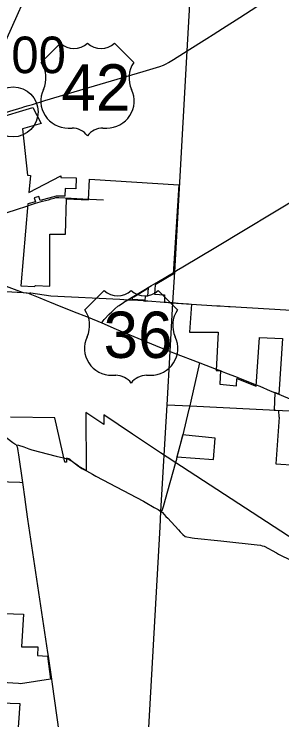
# Model space of a CAD drawing. Extents: x 1729596 to 1934326, y 644115 to 911751.
# Drawn here: x 1815592 to 1823628, y 824548 to 845758 of the extents above; entities that cross this region are included whole.
import ezdxf

# ---------------------------------------------------------------- set-up
doc = ezdxf.new("R2010")
doc.units = 0
for name, color, linetype in [('Default', 7, 'Continuous'), ('GM_X_City_Street', 7, 'Continuous'), ('GM_X_Corporation', 7, 'Continuous'), ('GM_X_County_Road', 7, 'Continuous'), ('GM_X_State_Route', 7, 'Continuous'), ('GM_X_Township', 7, 'Continuous'), ('GM_X_Township_Road', 7, 'Continuous'), ('GM_X_US_Route', 7, 'Continuous'), ('GM_X_US_Shield', 7, 'Continuous')]:
    doc.layers.add(name, color=color, linetype=linetype)

msp = doc.modelspace()

# ---------------------------------------------------------------- linework, layer by layer
at = {"layer": 'Default'}
msp.add_circle((1815562, 842819), 750, dxfattribs=at)
at = {"layer": 'GM_X_City_Street'}
for points in [[(1813943, 839357), (1814716, 839584), (1815637, 839875), (1816002, 840001), (1816050, 840016)], [(1816021, 837368), (1816062, 837380), (1816090, 837381), (1816690, 837295), (1818762, 837191), (1819004, 837172)], [(1819004, 837172), (1819134, 837175), (1819472, 837149)], [(1819524, 837145), (1819604, 837139), (1820097, 837105)], [(1820652, 833075), (1820849, 833886), (1820873, 833984), (1820908, 834123), (1821164, 835274)], [(1817072, 832421), (1817099, 832415), (1817170, 832396)], [(1820438, 832263), (1820471, 832388), (1820478, 832416)]]:
    msp.add_lwpolyline(points, dxfattribs=at)
at = {"layer": 'GM_X_Corporation'}
for points in [[(1815016, 842610), (1816153, 842951), (1816403, 842466), (1815846, 842310), (1815989, 840914), (1816080, 840907), (1816036, 840400), (1816992, 840894), (1816992, 840847), (1817454, 840834), (1817443, 840510), (1817122, 840521), (1817110, 840282), (1816854, 840287), (1816369, 840160), (1816334, 840281), (1816195, 840241), (1816230, 840120), (1816007, 840055), (1815797, 837596), (1816204, 837568), (1816230, 837602), (1816665, 837580), (1816663, 839149), (1817135, 839141), (1817168, 840204), (1817823, 840172), (1817852, 840795), (1820532, 840624), (1820362, 837942), (1819824, 837620), (1819808, 837343), (1820104, 837324), (1820105, 837097), (1820468, 837073), (1820915, 837044), (1820852, 836201), (1821717, 836195), (1821656, 835046), (1821781, 835050), (1821769, 834633), (1822268, 834587), (1822281, 834808), (1822854, 834577), (1822956, 836039), (1823645, 836005), (1823540, 834336), (1823415, 834383), (1823397, 833851), (1823528, 833845), (1823535, 833649), (1823542, 833643), (1823444, 832245), (1824058, 832202)], [(1824031, 829939), (1819982, 832569), (1819654, 832789), (1819142, 833130), (1818281, 833718), (1818286, 833421), (1817747, 833788), (1817756, 832046), (1817667, 832094), (1817528, 832169), (1817473, 832209), (1817387, 832271), (1817263, 832384), (1817160, 832409), (1817160, 832297), (1817114, 832297), (1816814, 833623), (1815483, 833646)], [(1811009, 827882), (1815869, 827729), (1815809, 826748), (1816301, 826739), (1816293, 826483), (1816593, 826467), (1816684, 825773), (1815779, 825630), (1815726, 825640), (1815222, 825670)], [(1815180, 825063), (1815759, 825045), (1815628, 823017)]]:
    msp.add_lwpolyline(points, dxfattribs=at)
for points in [[(1819526, 837135), (1819535, 837296), (1819609, 837287), (1819623, 837519), (1819182, 837253), (1819135, 837235), (1819132, 837195), (1819476, 837173), (1819474, 837138)], [(1820476, 832454), (1821573, 832377), (1821623, 833012), (1820645, 833115), (1820621, 833009), (1820595, 832898)]]:
    msp.add_lwpolyline(points, close=True, dxfattribs=at)
at = {"layer": 'GM_X_County_Road'}
for points in [[(1814101, 842164), (1814760, 843649), (1815210, 844662), (1816320, 847160), (1816351, 847229), (1816426, 847398), (1816452, 847455)], [(1819472, 837149), (1819494, 837147), (1819524, 837145)], [(1820097, 837105), (1820163, 837101), (1820305, 837091)], [(1820305, 837091), (1820358, 837087), (1820517, 837071), (1820825, 837049)], [(1820825, 837049), (1820913, 837042), (1821680, 836994), (1821777, 836987), (1822028, 836972), (1822074, 836969)], [(1822074, 836969), (1824417, 836829)], [(1815650, 832818), (1815609, 832834), (1815550, 832877), (1815172, 833164), (1814933, 833350), (1814868, 833401), (1814625, 833586), (1814048, 834029), (1813975, 834088), (1813947, 834115), (1813922, 834145), (1813910, 834164)], [(1815650, 832818), (1815681, 832754), (1815696, 832701), (1815707, 832636), (1815724, 832514), (1815839, 831685), (1815910, 831182), (1815924, 831087), (1815997, 830585), (1816596, 826570), (1816611, 826462)], [(1816611, 826462), (1816709, 825776), (1816721, 825692)], [(1816721, 825692), (1817014, 823620), (1817048, 823324), (1817073, 823174), (1817376, 823219), (1817730, 823275), (1817816, 823287), (1818034, 823286), (1819167, 823275), (1819464, 823265), (1819525, 823263), (1819568, 823254)]]:
    msp.add_lwpolyline(points, dxfattribs=at)
at = {"layer": 'GM_X_State_Route'}
for points in [[(1820468, 838053), (1820655, 838166), (1821648, 838759), (1824240, 840319)], [(1813129, 838411), (1813340, 838332), (1813710, 838195), (1813746, 838181), (1814002, 838086), (1814499, 837901), (1814621, 837856), (1814811, 837785), (1814899, 837753), (1814979, 837723), (1815024, 837706), (1815354, 837583), (1815358, 837582), (1815752, 837432), (1815862, 837391)], [(1819182, 837279), (1819382, 837398), (1819716, 837599), (1819921, 837722), (1820411, 838018), (1820468, 838053)], [(1818870, 837089), (1818887, 837100), (1819004, 837172), (1819182, 837279)], [(1818616, 836904), (1818704, 836977), (1818742, 837004), (1818870, 837089)], [(1818221, 836484), (1818267, 836536), (1818298, 836577), (1818447, 836739), (1818522, 836815), (1818613, 836902), (1818616, 836904)]]:
    msp.add_lwpolyline(points, dxfattribs=at)
at = {"layer": 'GM_X_Township'}
for points in [[(1820182, 834021), (1820274, 835623), (1820357, 837080), (1820411, 838018), (1820789, 844650), (1820950, 847472), (1821204, 851968), (1821306, 853784), (1821743, 860915)], [(1819571, 823253), (1819973, 830336), (1820000, 830812), (1820182, 834021), (1820873, 833984), (1824840, 833781), (1824931, 833776), (1825545, 833759), (1825602, 833752), (1827748, 833636), (1831529, 833453), (1832327, 833414), (1835297, 833263), (1838313, 833094), (1838887, 833066), (1838934, 833082), (1842052, 832856), (1843609, 832772), (1846971, 832575), (1846863, 830918), (1846854, 830870), (1846509, 825988), (1846205, 821378)]]:
    msp.add_lwpolyline(points, dxfattribs=at)
at = {"layer": 'GM_X_Township_Road'}
for points in [[(1816050, 840016), (1816237, 840077), (1816448, 840141), (1816624, 840179), (1816708, 840206), (1816793, 840229), (1816843, 840243), (1816931, 840248), (1817301, 840230), (1817654, 840208), (1818276, 840179)], [(1820478, 832416), (1820578, 832795), (1820650, 833063), (1820652, 833075)], [(1815650, 832818), (1815723, 832800), (1815882, 832749), (1816035, 832698), (1816127, 832661), (1816854, 832473), (1817072, 832421)], [(1817170, 832396), (1817189, 832391), (1817247, 832372), (1817293, 832347), (1817314, 832333), (1817347, 832309), (1817435, 832240), (1817523, 832171), (1817551, 832151), (1817625, 832105), (1817729, 832048)], [(1820010, 830806), (1820037, 830840), (1820072, 830957), (1820135, 831180), (1820436, 832256), (1820438, 832263)], [(1811732, 831884), (1812190, 831865), (1812461, 831851), (1813734, 831797), (1813810, 831792), (1815017, 831728), (1815419, 831700), (1815762, 831691), (1815839, 831685)], [(1817729, 832048), (1817764, 832029), (1817942, 831931), (1818048, 831874), (1819478, 831120), (1819525, 831094), (1819797, 830932), (1819854, 830901), (1819916, 830867), (1820000, 830812), (1820010, 830806)], [(1820010, 830806), (1820042, 830778), (1820145, 830662), (1820205, 830609), (1820524, 830257), (1820580, 830196), (1820656, 830123), (1820728, 830055), (1820936, 830023), (1821010, 830011), (1821798, 829929), (1821888, 829919), (1822885, 829807), (1822989, 829796), (1823040, 829782), (1823095, 829767), (1823466, 829565), (1823529, 829531), (1824286, 829155), (1824340, 829128), (1824755, 828908)]]:
    msp.add_lwpolyline(points, dxfattribs=at)
at = {"layer": 'GM_X_US_Route'}
for points in [[(1815985, 842997), (1816140, 843045), (1816516, 843159), (1818004, 843604), (1819466, 844036), (1819970, 844186), (1820078, 844226), (1820154, 844261), (1820230, 844302), (1820378, 844395), (1820678, 844582), (1820789, 844650), (1821371, 845021), (1821564, 845146), (1821850, 845326), (1822366, 845660), (1822875, 845990), (1823392, 846332), (1823964, 846703), (1824557, 847070), (1825025, 847354), (1825562, 847681), (1826103, 848010), (1826523, 848267)], [(1815275, 842785), (1815313, 842796), (1815429, 842831), (1815459, 842839), (1815834, 842951)], [(1815834, 842951), (1815888, 842967), (1815985, 842997)], [(1813063, 837594), (1813186, 837584), (1813478, 837560), (1813723, 837544), (1813782, 837540), (1814136, 837513), (1814468, 837489), (1815015, 837449), (1815359, 837423), (1815684, 837401), (1815707, 837400)], [(1815707, 837400), (1815862, 837391)], [(1815862, 837391), (1815950, 837382), (1815954, 837381)], [(1815954, 837381), (1815981, 837378), (1816021, 837368), (1816060, 837353), (1816163, 837312), (1816361, 837232), (1816558, 837152)], [(1816558, 837152), (1816658, 837111), (1816823, 837044), (1817348, 836830), (1817814, 836649), (1818221, 836484)], [(1818221, 836484), (1818657, 836290), (1819840, 835798), (1820274, 835623), (1820373, 835583), (1821164, 835274), (1821658, 835092), (1821742, 835058)], [(1821742, 835058), (1821837, 835019), (1821938, 834981)], [(1821938, 834981), (1822282, 834851), (1822381, 834811)], [(1822381, 834811), (1822857, 834621), (1822968, 834573)], [(1822968, 834573), (1823279, 834440), (1823404, 834391), (1823504, 834351)], [(1823504, 834351), (1823539, 834337), (1823602, 834310)], [(1823602, 834310), (1823863, 834198), (1823927, 834172), (1823961, 834158), (1824572, 833896)]]:
    msp.add_lwpolyline(points, dxfattribs=at)
at = {"layer": 'GM_X_US_Shield'}
for p, q in [((1816981, 844887), (1816401, 844307)), ((1816981, 844887), (1816401, 844307)), ((1819186, 844307), (1818606, 844887)), ((1819186, 844307), (1818606, 844887)), ((1817213, 842334), (1817329, 842334)), ((1817213, 842334), (1817329, 842334)), ((1818258, 842334), (1818374, 842334)), ((1818258, 842334), (1818374, 842334)), ((1818293, 837455), (1817713, 836875)), ((1818293, 837455), (1817713, 836875)), ((1820497, 836875), (1819917, 837455)), ((1820497, 836875), (1819917, 837455)), ((1818525, 834903), (1818641, 834903)), ((1818525, 834903), (1818641, 834903)), ((1819569, 834903), (1819685, 834903)), ((1819569, 834903), (1819685, 834903))]:
    msp.add_line(p, q, dxfattribs=at)
for centre, radius, start, end in [((1817387, 845301), 580, 225.573, 314.427), ((1817387, 845301), 580, 225.573, 314.427), ((1818200, 845301), 580, 225.573, 314.427), ((1818200, 845301), 580, 225.573, 314.427), ((1815736, 843841), 812, 334.5471, 35.0009), ((1815736, 843841), 812, 334.5471, 35.0009), ((1819851, 843841), 812, 144.9991, 205.4529), ((1819851, 843841), 812, 144.9991, 205.4529), ((1817204, 843147), 812, 154.8319, 270.6383), ((1817204, 843147), 812, 154.8319, 270.6383), ((1818383, 843147), 812, 269.3617, 25.1681), ((1818383, 843147), 812, 269.3617, 25.1681), ((1817329, 841754), 580, 36.8699, 90), ((1817329, 841754), 580, 36.8699, 90), ((1818258, 841754), 580, 90, 143.1301), ((1818258, 841754), 580, 90, 143.1301), ((1818699, 837870), 580, 225.573, 314.427), ((1818699, 837870), 580, 225.573, 314.427), ((1819511, 837870), 580, 225.573, 314.427), ((1819511, 837870), 580, 225.573, 314.427), ((1817047, 836409), 812, 334.5471, 35.0009), ((1817047, 836409), 812, 334.5471, 35.0009), ((1821162, 836409), 812, 144.9991, 205.4529), ((1821162, 836409), 812, 144.9991, 205.4529), ((1818516, 835715), 812, 154.8319, 270.6383), ((1818516, 835715), 812, 154.8319, 270.6383), ((1819694, 835715), 812, 269.3617, 25.1681), ((1819694, 835715), 812, 269.3617, 25.1681), ((1818641, 834323), 580, 36.8699, 90), ((1818641, 834323), 580, 36.8699, 90), ((1819569, 834323), 580, 90, 143.1301), ((1819569, 834323), 580, 90, 143.1301)]:
    msp.add_arc(centre, radius, start, end, dxfattribs=at)

# ---------------------------------------------------------------- texts
at = {"layer": 'Default'}
msp.add_text('10.00', height=1100, dxfattribs=at).set_placement((1813464, 843983))
at = {"layer": 'GM_X_US_Shield'}
for s, p in [('42', (1817010, 842857)), ('42', (1817010, 842857)), ('36', (1818277, 835425)), ('36', (1818277, 835425))]:
    msp.add_text(s, height=1392.2, dxfattribs=at).set_placement(p)

doc.saveas('drawing.dxf')
